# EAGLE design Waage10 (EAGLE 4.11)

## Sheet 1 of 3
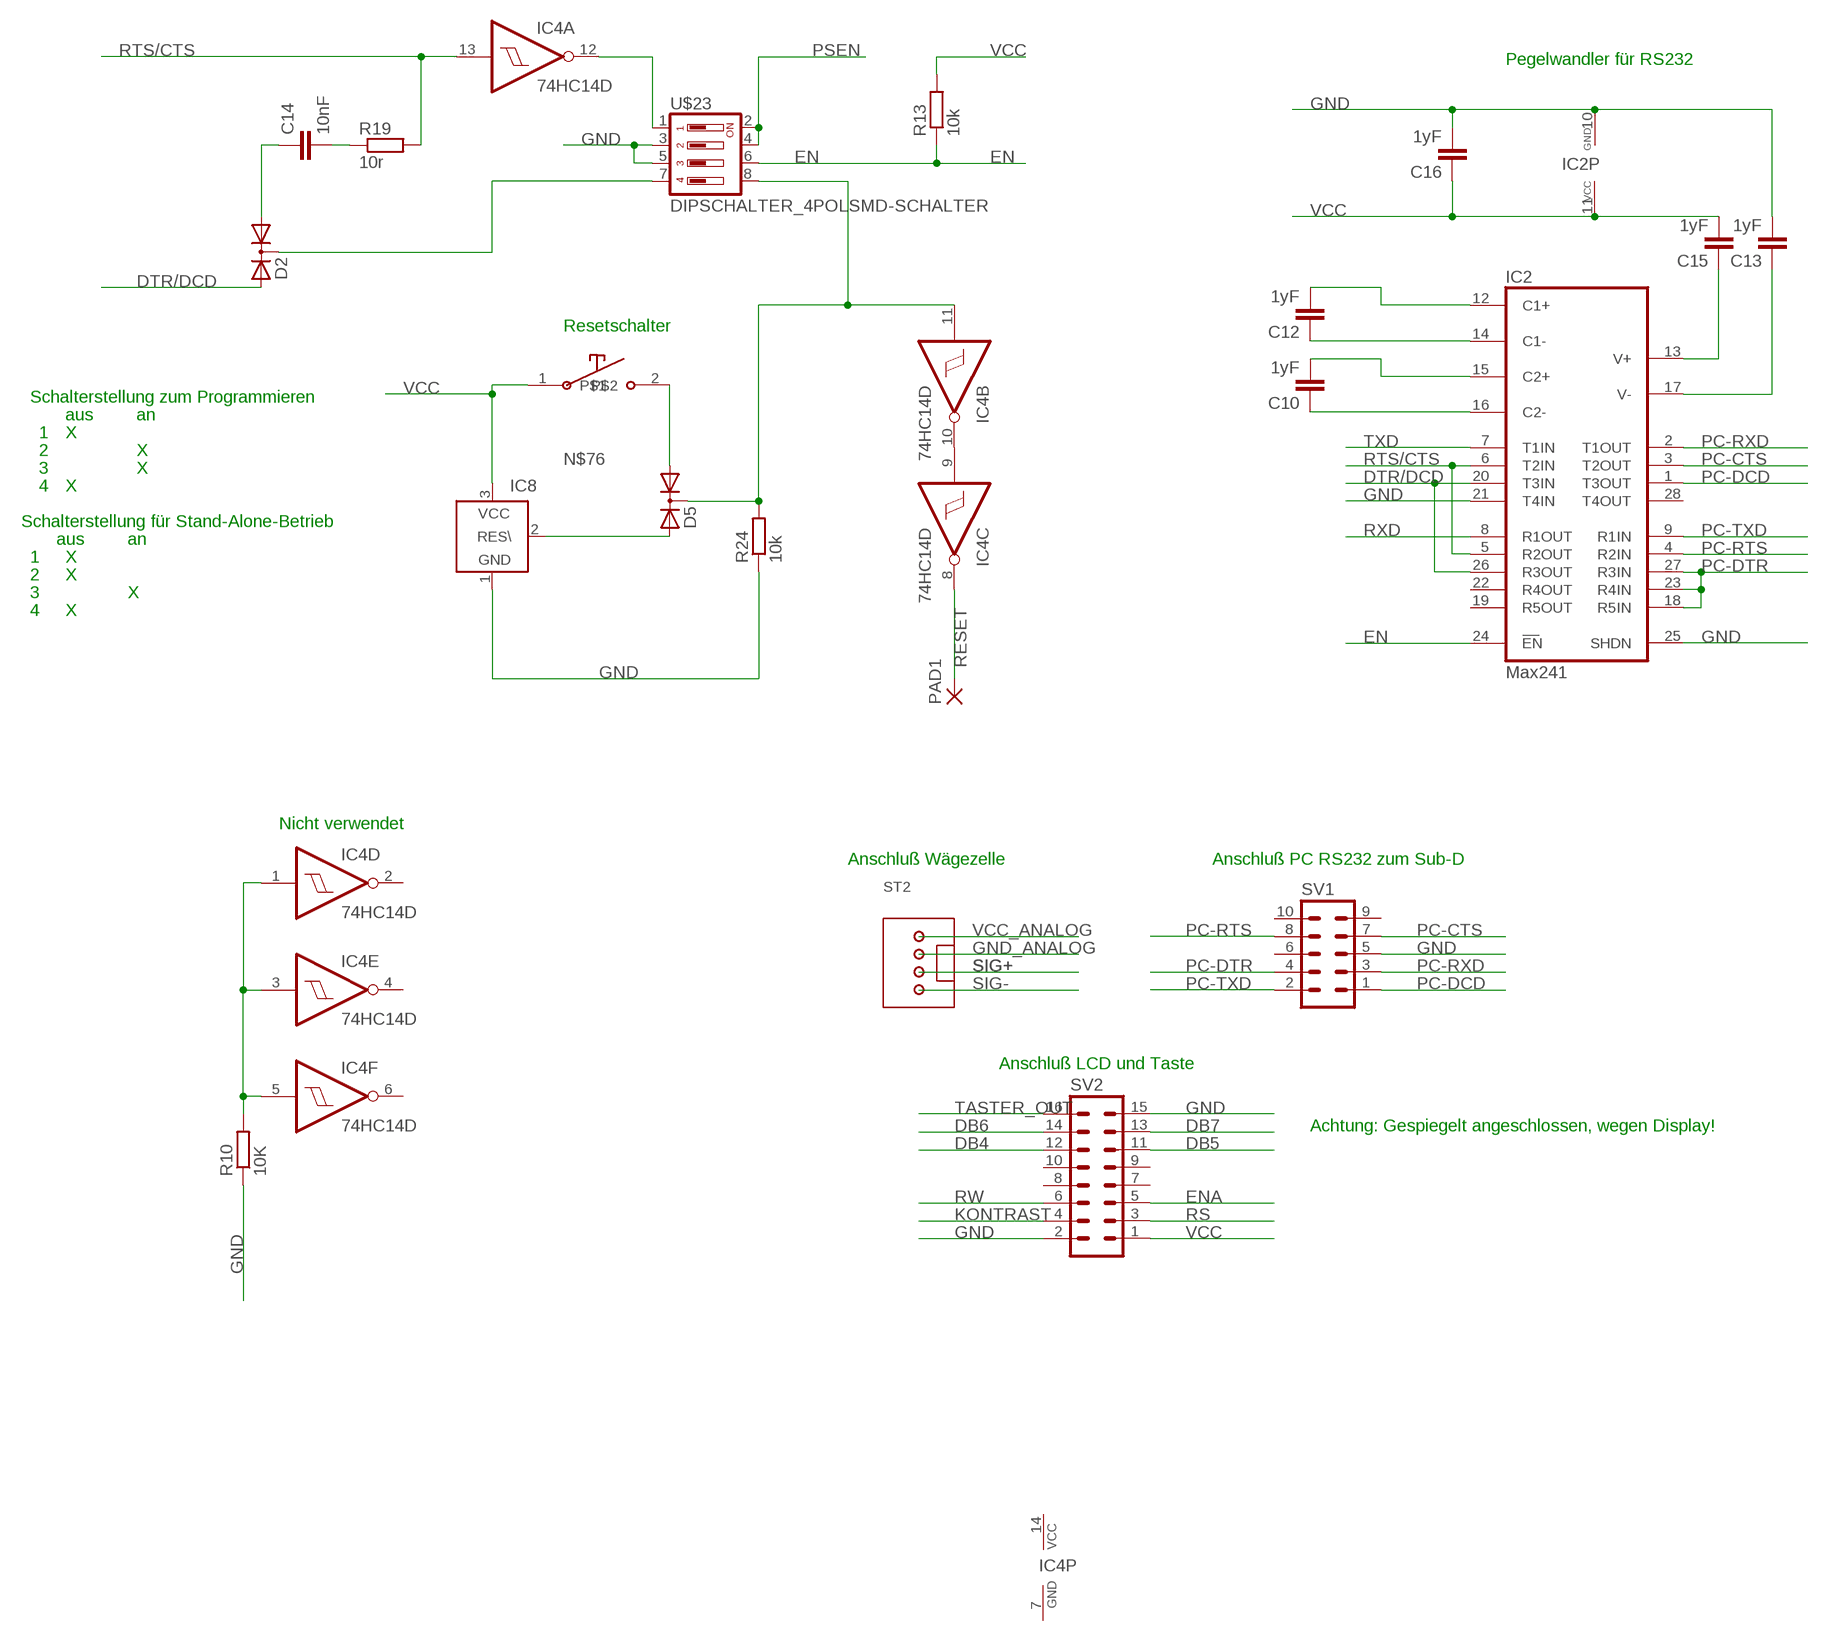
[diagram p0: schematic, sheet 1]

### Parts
C10  1yF  C-EUC1206  [C1206]
C12  1yF  C-EUC1206  [C1206]
C13  1yF  C-EUC1206  [C1206]
C14  10nF  C-EUC1206  [C1206]
C15  1yF  C-EUC1206  [C1206]
C16  1yF  C-EUC1206  [C1206]
D2  DIODE-2AC|CASOT23  [SOT23]
D5  DIODE-2AC|CASOT23  [SOT23]
IC2  Max241  MAX241ECWISSOP  [SSOP28]
IC4  74HC14D  [SO14]
IC8  TCM809  [SOT23B-3]
PAD1  SMD2  [SMD2]
R10  10K  R-EU_M1206  [M1206]
R13  10k  R-EU_M1206  [M1206]
R19  10r  R-EU_R1206  [R1206]
R24  10k  R-EU_R1206  [R1206]
ST2  MOLEX_04  [MOL_04SS]
SV1  ML10  [ML10]
SV2  ML16  [ML16]
U$4  TASTESMD-TASTE  [SMD-TASTE]
U$23  DIPSCHALTER_4POLSMD-SCHALTER  [SMD_DIP4]

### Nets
DB4: SV2.12 ; also sheet 2
DB5: SV2.11 ; also sheet 2
DB6: SV2.14 ; also sheet 2
DB7: SV2.13 ; also sheet 2
DTR/DCD: D2.2(A2) IC2.20(T3IN) IC2.26(R3OUT)
EN: IC2.24(EN) R13.1 U$23.6
ENA: SV2.5 ; also sheet 2
GND: C13.2 C16.2 IC2.10(GND) IC2.21(T4IN) IC2.25(SHDN) IC8.1(GND) R10.1 R24.1 SV1.5 SV2.2 SV2.15 U$23.3 U$23.5 ; also sheet 2,3
GND_ANALOG: ST2.2 ; also sheet 2,3
KONTRAST: SV2.4 ; also sheet 2
N$5: IC4.1(D:I) IC4.3(E:I) IC4.5(F:I) R10.2
N$7: IC4.9(C:I) IC4.10(B:O)
N$8: C14.1 D2.1(A1)
N$10: C14.2 R19.1
N$12: C10.2 IC2.15(C2+)
N$21: C12.1 IC2.14(C1-)
N$23: C12.2 IC2.12(C1+)
N$24: C10.1 IC2.16(C2-)
N$25: C13.1 IC2.17(V-)
N$26: C15.1 IC2.13(V+)
N$30: D2.3(C) U$23.7
N$76: D5.1(A1) U$4.2
N$78: D5.3(C) IC4.11(B:I) R24.2 U$23.8
N$84: IC4.12(A:O) U$23.1
N$87: D5.2(A2) IC8.2(RES\)
PC-CTS: IC2.3(T2OUT) SV1.7
PC-DCD: IC2.1(T3OUT) SV1.1
PC-DTR: IC2.18(R5IN) IC2.23(R4IN) IC2.27(R3IN) SV1.4
PC-RTS: IC2.4(R2IN) SV1.8
PC-RXD: IC2.2(T1OUT) SV1.3
PC-TXD: IC2.9(R1IN) SV1.2
PSEN: U$23.2 U$23.4 ; also sheet 2
RESET: IC4.8(C:O) PAD1.1(P) ; also sheet 2
RS: SV2.3 ; also sheet 2
RTS/CTS: IC2.5(R2OUT) IC2.6(T2IN) IC4.13(A:I) R19.2
RW: SV2.6 ; also sheet 2
RXD: IC2.8(R1OUT) ; also sheet 2
SIG+: ST2.3 ; also sheet 2
SIG-: ST2.4 ; also sheet 2
TASTER_OUT: SV2.16 ; also sheet 2
TXD: IC2.7(T1IN) ; also sheet 2
VCC: C15.2 C16.1 IC2.11(VCC) IC8.3(VCC) R13.2 SV2.1 U$4.1 ; also sheet 2,3
VCC_ANALOG: ST2.1 ; also sheet 2,3
Unconnected: IC2.19(R5OUT) IC2.22(R4OUT) IC2.28(T4OUT) SV1.6 SV1.9 SV1.10 SV2.7 SV2.8 SV2.9 SV2.10

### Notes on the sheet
- Pegelwandler für RS232
- Resetschalter
- Schalterstellung zum Programmieren
- aus | an
- 1 | X
- 2 | X
- 3 | X
- 4 | X
- Schalterstellung für Stand-Alone-Betrieb
- aus | an
- 1 | X
- 2 | X
- 3 | X
- 4 | X
- Nicht verwendet
- Anschluß Wägezelle | Anschluß PC RS232 zum Sub-D
- Anschluß LCD und Taste
- Achtung: Gespiegelt angeschlossen, wegen Display!

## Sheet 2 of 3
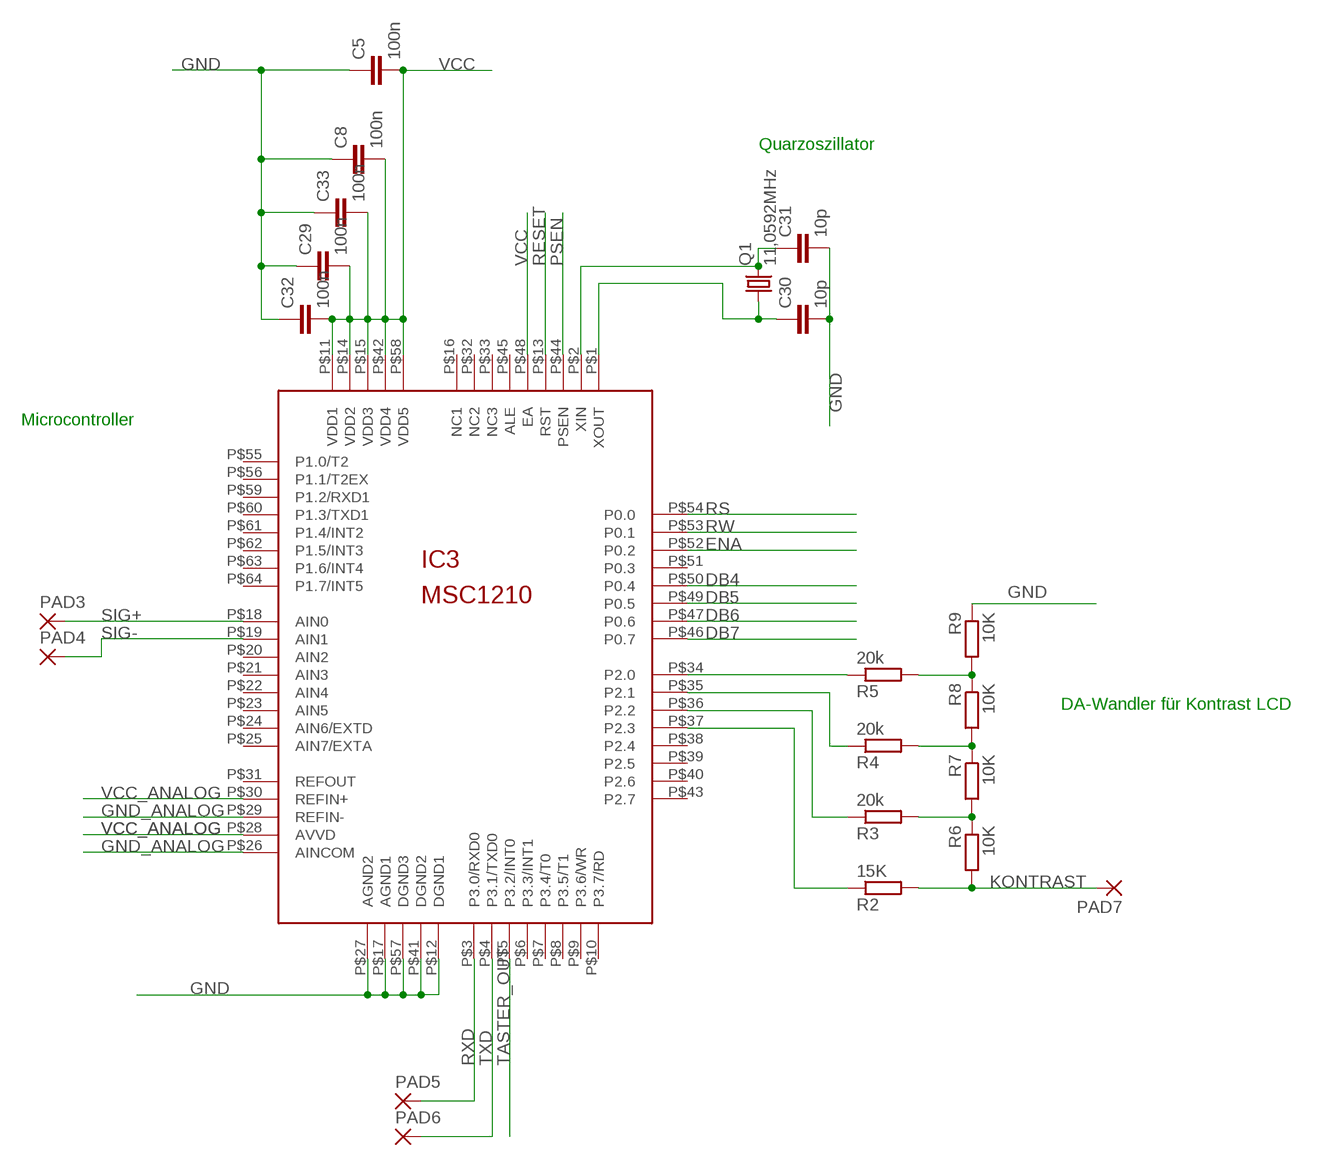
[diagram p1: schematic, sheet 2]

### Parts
C5  100n  C-EUC1206  [C1206]
C8  100n  C-EUC1206  [C1206]
C29  100n  C-EUC1206  [C1206]
C30  10p  C-EUC0805  [C0805]
C31  10p  C-EUC0805  [C0805]
C32  100n  C-EUC1206  [C1206]
C33  100n  C-EUC1206  [C1206]
IC3  MSC1210  MSC1210SMD  [S-PQFP-G64]
PAD3  SMD2  [SMD2]
PAD4  SMD2  [SMD2]
PAD5  SMD2  [SMD2]
PAD6  SMD2  [SMD2]
PAD7  SMD2  [SMD2]
Q1  11,0592MHz  CRYTALHC49UP  [HC49UP]
R2  15K  R-EU_M1206  [M1206]
R3  20k  R-EU_M1206  [M1206]
R4  20k  R-EU_M1206  [M1206]
R5  20k  R-EU_M1206  [M1206]
R6  10K  R-EU_M1206  [M1206]
R7  10K  R-EU_M1206  [M1206]
R8  10K  R-EU_M1206  [M1206]
R9  10K  R-EU_M1206  [M1206]

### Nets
DB4: IC3.P$50(P0.4) ; also sheet 1
DB5: IC3.P$49(P0.5) ; also sheet 1
DB6: IC3.P$47(P0.6) ; also sheet 1
DB7: IC3.P$46(P0.7) ; also sheet 1
ENA: IC3.P$52(P0.2) ; also sheet 1
GND: C5.1 C8.1 C29.1 C30.2 C31.2 C32.1 C33.1 IC3.P$12(DGND1) IC3.P$17(AGND1) IC3.P$27(AGND2) IC3.P$41(DGND2) IC3.P$57(DGND3) R9.1 ; also sheet 1,3
GND_ANALOG: IC3.P$26(AINCOM) IC3.P$29(REFIN-) ; also sheet 1,3
KONTRAST: PAD7.1(P) R2.2 R6.2 ; also sheet 1
N$1: IC3.P$34(P2.0) R5.1
N$3: C31.1 IC3.P$2(XIN) Q1.2
N$4: C30.1 IC3.P$1(XOUT) Q1.1
N$15: IC3.P$36(P2.2) R3.1
N$16: IC3.P$35(P2.1) R4.1
N$18: R3.2 R6.1 R7.2
N$19: R4.2 R7.1 R8.2
N$20: R5.2 R8.1 R9.2
N$28: IC3.P$37(P2.3) R2.1
PSEN: IC3.P$44(PSEN) ; also sheet 1
RESET: IC3.P$13(RST) ; also sheet 1
RS: IC3.P$54(P0.0) ; also sheet 1
RW: IC3.P$53(P0.1) ; also sheet 1
RXD: IC3.P$3(P3.0/RXD0) PAD5.1(P) ; also sheet 1
SIG+: IC3.P$18(AIN0) PAD3.1(P) ; also sheet 1
SIG-: IC3.P$19(AIN1) PAD4.1(P) ; also sheet 1
TASTER_OUT: IC3.P$5(P3.2/INT0) ; also sheet 1
TXD: IC3.P$4(P3.1/TXD0) PAD6.1(P) ; also sheet 1
VCC: C5.2 C8.2 C29.2 C32.2 C33.2 IC3.P$11(VDD1) IC3.P$14(VDD2) IC3.P$15(VDD3) IC3.P$42(VDD4) IC3.P$48(EA) IC3.P$58(VDD5) ; also sheet 1,3
VCC_ANALOG: IC3.P$28(AVVD) IC3.P$30(REFIN+) ; also sheet 1,3
Unconnected: IC3.P$6(P3.3/INT1) IC3.P$7(P3.4/T0) IC3.P$8(P3.5/T1) IC3.P$9(P3.6/WR) IC3.P$10(P3.7/RD) IC3.P$16(NC1) IC3.P$20(AIN2) IC3.P$21(AIN3) IC3.P$22(AIN4) IC3.P$23(AIN5) IC3.P$24(AIN6/EXTD) IC3.P$25(AIN7/EXTA) IC3.P$31(REFOUT) IC3.P$32(NC2) IC3.P$33(NC3) IC3.P$38(P2.4) IC3.P$39(P2.5) IC3.P$40(P2.6) IC3.P$43(P2.7) IC3.P$45(ALE) IC3.P$51(P0.3) IC3.P$55(P1.0/T2) IC3.P$56(P1.1/T2EX) IC3.P$59(P1.2/RXD1) IC3.P$60(P1.3/TXD1) IC3.P$61(P1.4/INT2) IC3.P$62(P1.5/INT3) IC3.P$63(P1.6/INT4) IC3.P$64(P1.7/INT5)

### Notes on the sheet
- Quarzoszillator
- Microcontroller
- DA-Wandler für Kontrast LCD

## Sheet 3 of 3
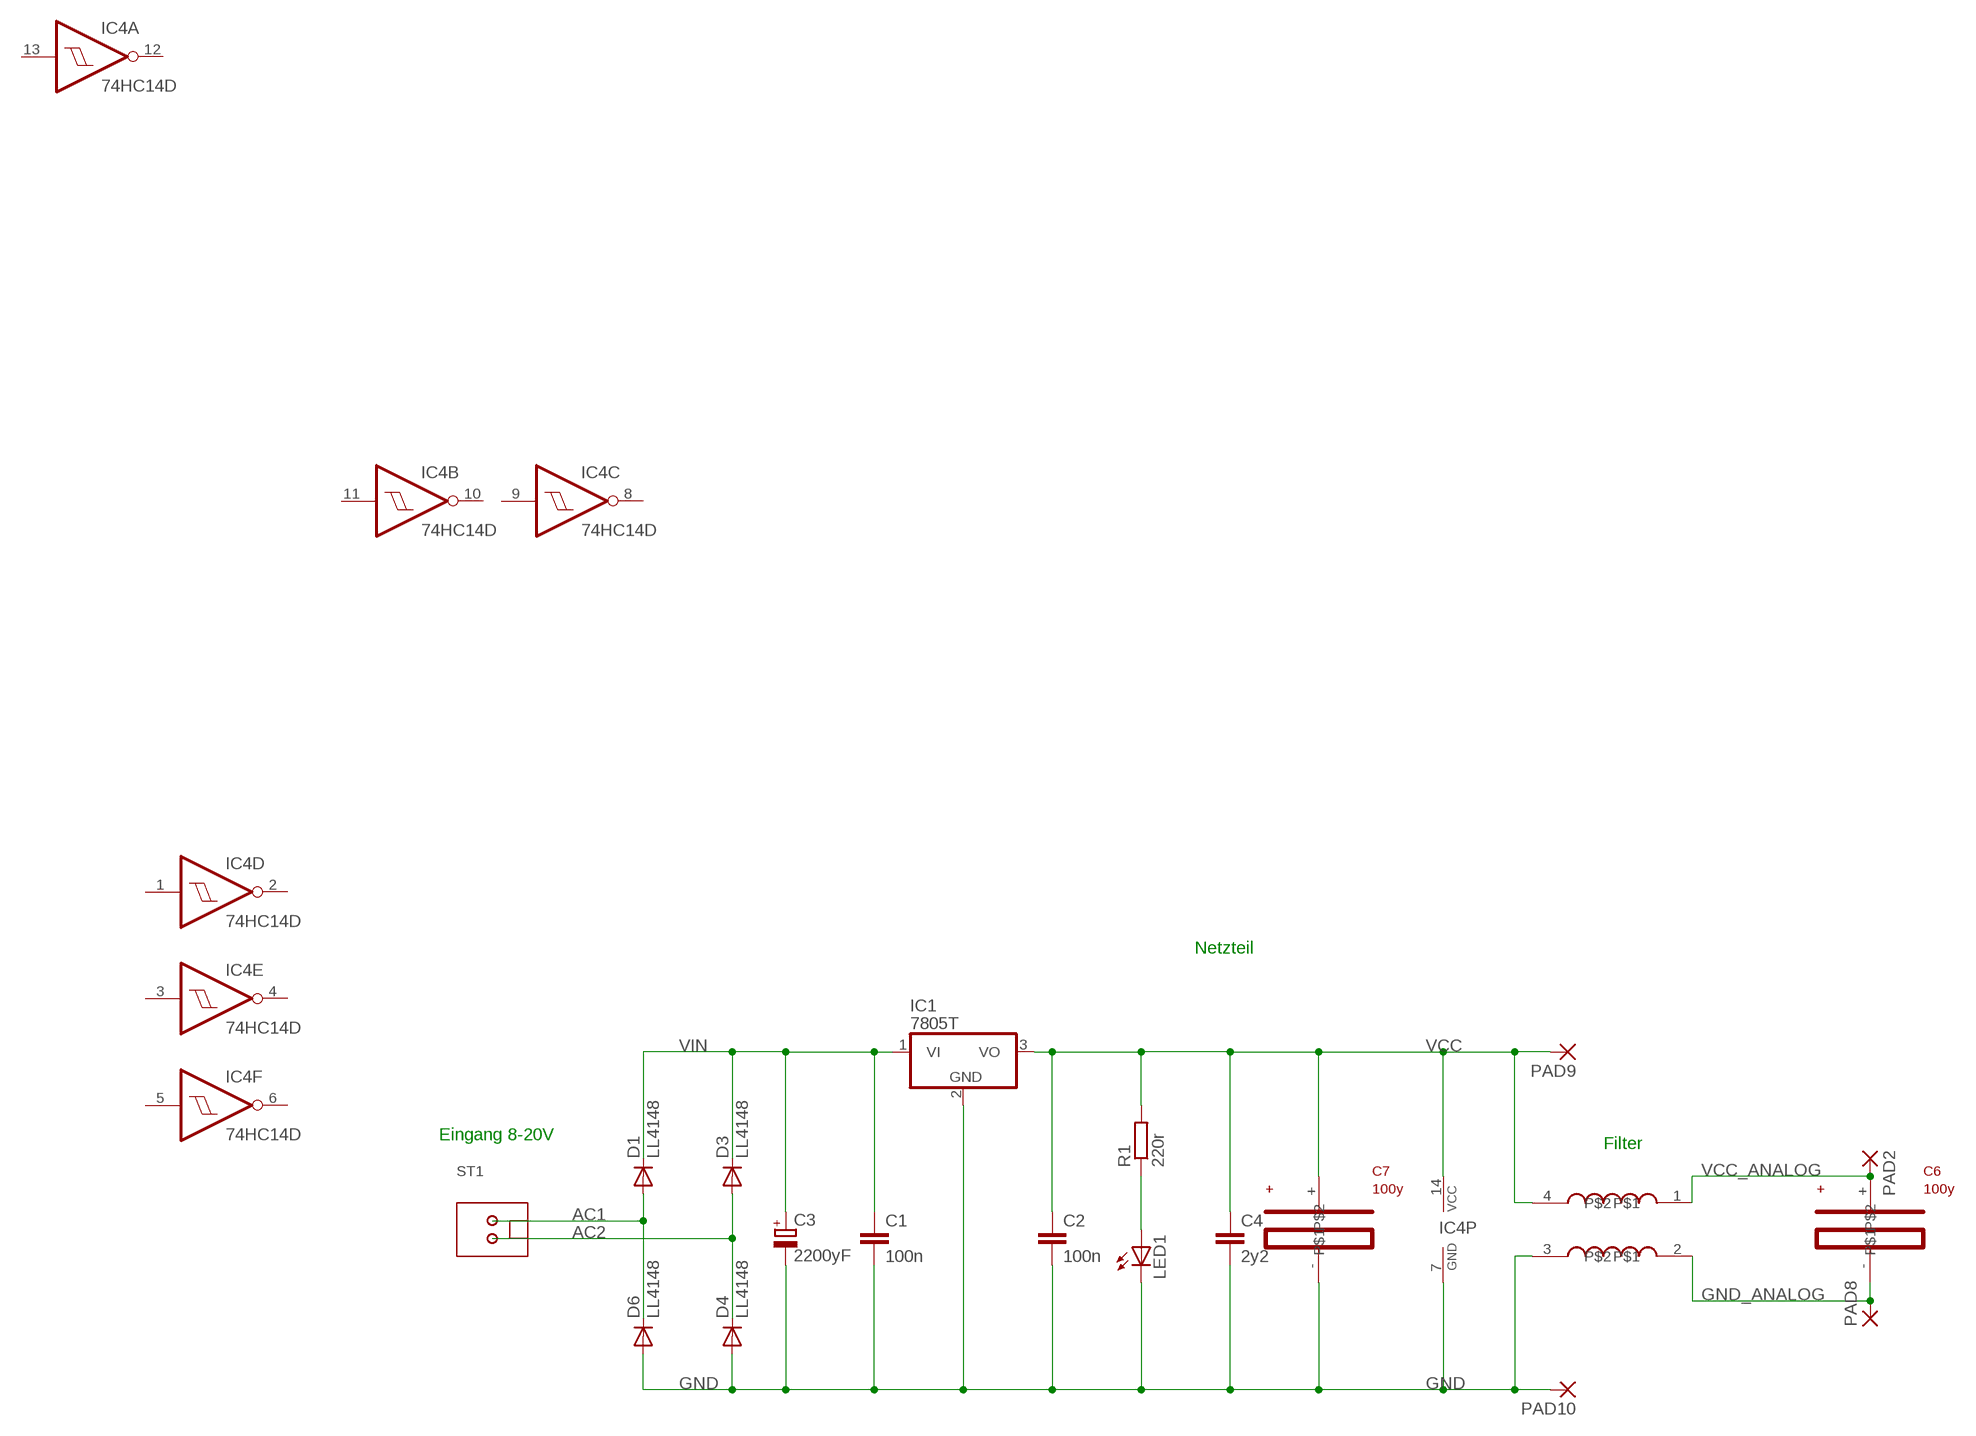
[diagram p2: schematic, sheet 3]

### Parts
C1  100n  C-EUC1206  [C1206]
C2  100n  C-EUC1206  [C1206]
C3  2200yF  CPOL-EUE7.5-16  [E7,5-16]
C4  2y2  C-EUC1206  [C1206]
C6  100y  ELKO_SMD  [SMD_D]
C7  100y  ELKO_SMD  [SMD_D]
D1  LL4148  DIODE-SOD80C  [SOD80C]
D3  LL4148  DIODE-SOD80C  [SOD80C]
D4  LL4148  DIODE-SOD80C  [SOD80C]
D6  LL4148  DIODE-SOD80C  [SOD80C]
F1  FILTER  [FILTER]
IC1  7805T  [TO220H]
LED1  LEDSMT1206  [1206]
PAD2  SMD2  [SMD2]
PAD8  SMD2  [SMD2]
PAD9  SMD2  [SMD2]
PAD10  SMD2  [SMD2]
R1  220r  R-EU_M1206  [M1206]
ST1  MOLEX_02  [MOL_02SS]

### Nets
AC1: D1.A D6.C ST1.1
AC2: D3.A D4.C ST1.2
GND: C1.2 C2.2 C3.- C4.2 C7.- D4.A D6.A F1.3 IC1.2(GND) IC4.7(P:GND) LED1.C PAD10.1(P) ; also sheet 1,2
GND_ANALOG: C6.- F1.2 PAD8.1(P) ; also sheet 1,2
N$13: LED1.A R1.1
VCC: C2.1 C4.1 C7.+ F1.4 IC1.3(VO) IC4.14(P:VCC) PAD9.1(P) R1.2 ; also sheet 1,2
VCC_ANALOG: C6.+ F1.1 PAD2.1(P) ; also sheet 1,2
VIN: C1.1 C3.+ D1.C D3.C IC1.1(VI)
Unconnected: IC4.2(D:O) IC4.4(E:O) IC4.6(F:O)

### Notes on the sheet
- Netzteil
- Eingang 8-20V
- Filter

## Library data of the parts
C1 C2 C4 C5 C8 C10 C12-C16 C29-C33 = rcl:C-EU: CAPACITOR, European symbol
C3 = rcl:CPOL-EU: POLARIZED CAPACITOR, European symbol
C6 C7 = FRANK:ELKO_SMD
D1 D3 D4 D6 = DIODE:DIODE-: DIODE
D2 D5 = DIODE:DIODE-2AC|CA: Dual DIODE Anode-Cathode|Cathode-Anode
F1 = FRANK:FILTER
IC1 = linear:78*: Positive VOLTAGE REGULATOR
IC2 = maxim:MAX241ECWI: RS232 TRANSEIVER Achtung: ECWI = SO28L ECAI=SSOP28
IC3 = FRANK:MSC1210
IC4 = 74xx-eu:74*14: Hex schmitt trigger INVERTER
IC8 = telcom:TCM809: POWER SUPPLY MONITOR replacement for Maxim MAX809 and MAX810
LED1 = led:LED: LED
PAD1-PAD10 = wirepad:SMD2: SMD PAD
Q1 = crystal:CRYTAL: CRYSTAL
R1-R10 R13 R19 R24 = rcl:R-EU_: RESISTOR, European symbol
ST1 = CONNECT:MOLEX_02
ST2 = CONNECT:MOLEX_04
SV1 = con-ml:ML10: HARTING
SV2 = con-ml:ML16: HARTING
U$4 = FRANK:TASTE
U$23 = FRANK:DIPSCHALTER_4POL

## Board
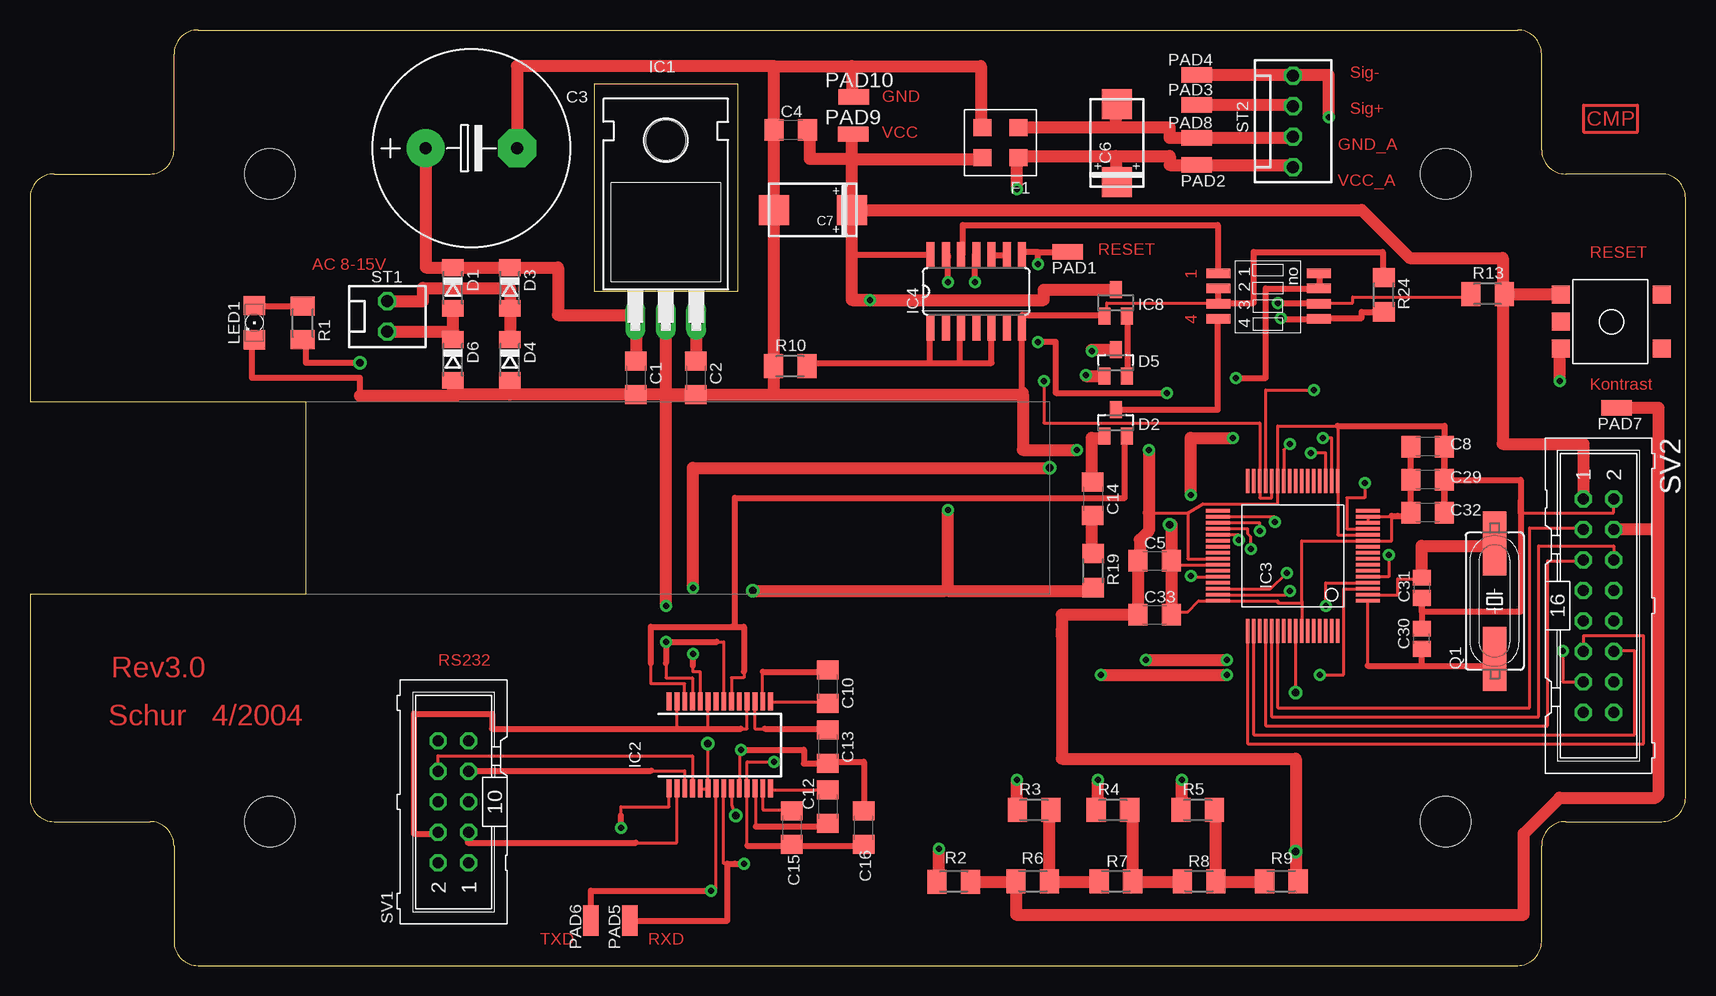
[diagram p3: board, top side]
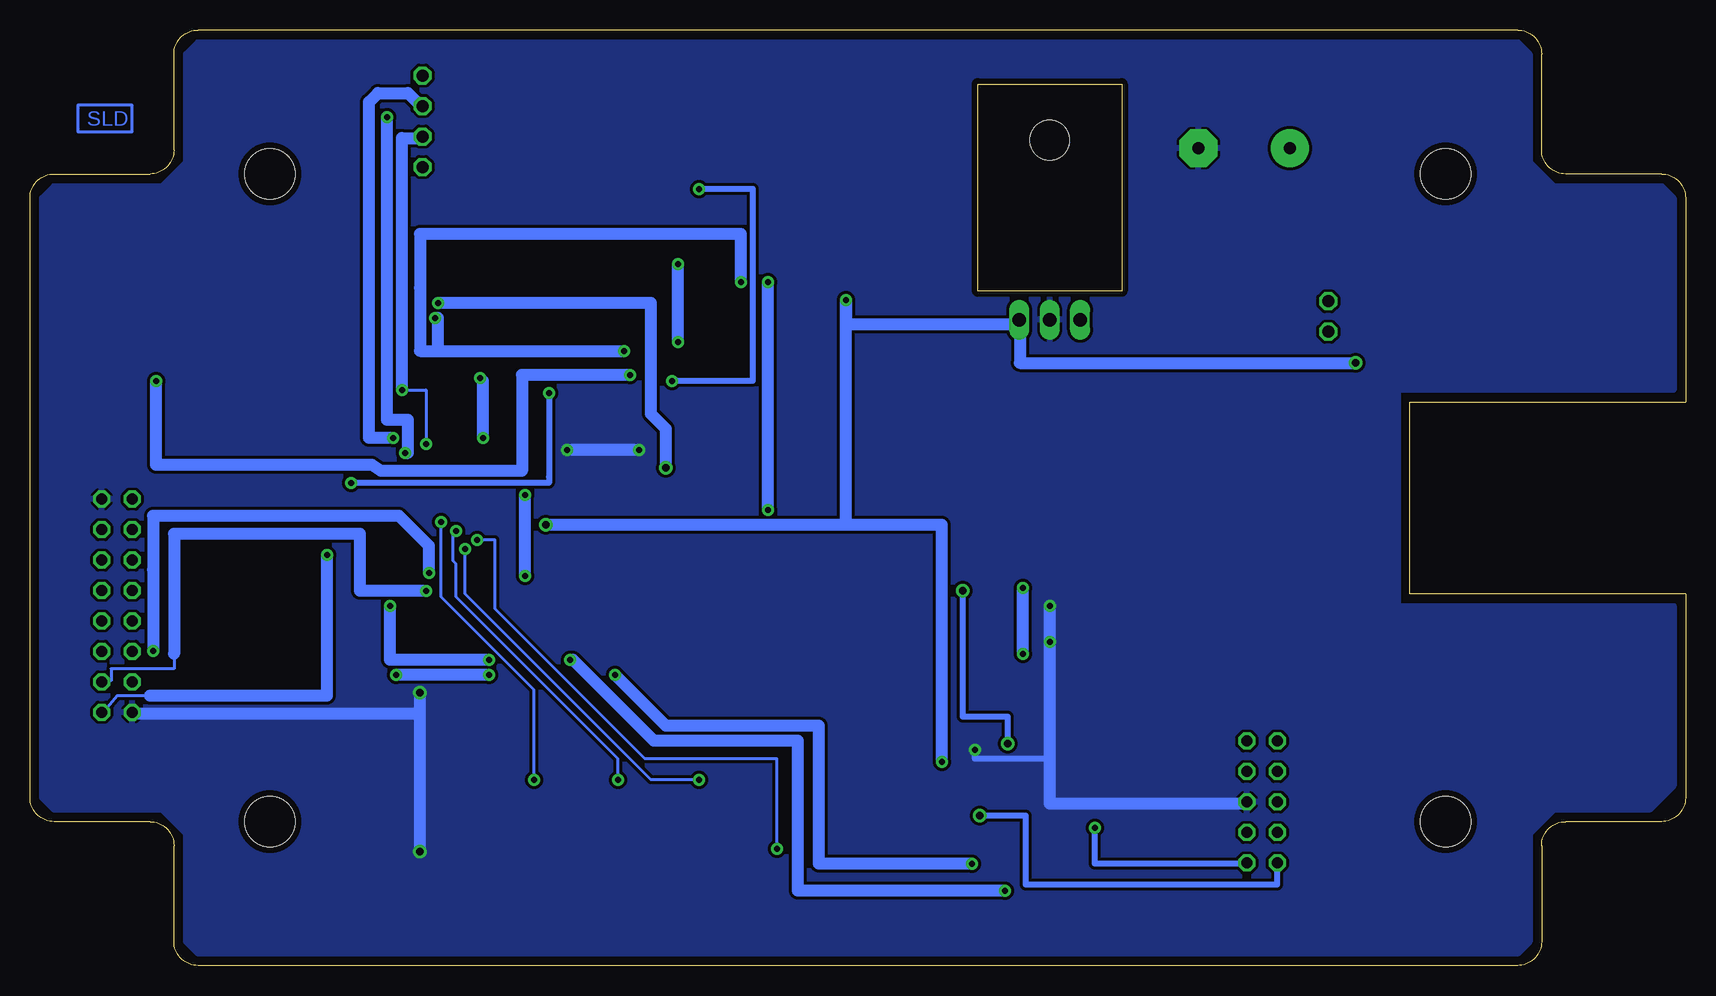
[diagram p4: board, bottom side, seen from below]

Size 138 x 78 mm. Coordinates in mm from the lower left corner, seen from the top.
Outline: 14,0 124,0 arc90 126,2 126,10 arc-90 128,12 136,12 arc90 138,14 138,64 arc90 136,66 128,66 arc-90 126,68 126,76 arc90 124,78 14,78 arc90 12,76 12,68 arc-90 10,66 2,66 arc90 0,64 0,47 23,47 23,31 0,31 0,14 arc90 2,12 10,12 arc-90 12,10 12,2 arc90 14,0
Outline: 47,56.25 59,56.25 59,73.5 47,73.5 47,56.25
Copper layers (1*16): Top 0.035mm / dielectric 1.5mm / Bottom 0.035mm
Design rules "default": minimum track width 0.25mm, minimum drill 0.4mm, track to track 0.25mm, track to pad 0.2mm, pad to pad 0.2mm, via to via 0.25mm, smd to smd 0.25mm, copper to edge 0.5mm, drill to drill 0.5mm, minimum pad ring 0.25mm, minimum via ring 0.25mm, stop-mask expansion 0.2mm, vias tented up to drill 0mil, thermal gap 0.2mm
Holes 4.2 mm at 20,12 20,66 118,66 118,12

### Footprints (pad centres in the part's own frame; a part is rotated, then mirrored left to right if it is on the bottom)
C1206 = smd 1.6 x 1.8: 1 -1.4,0; 2 1.4,0
E7,5-16 = drill 1.016 pad 3.15 round: + -3.81,0 | drill 1.016 pad 3.15 octagon: - 3.81,0
SMD_D = smd 2.5 x 2.5: + 0,0; - 6.5,0
C0805 = smd 1.3 x 1.5: 1 -0.85,0; 2 0.85,0
SOD80C = smd 1.4 x 1.8: A 1.7,0; C -1.7,0
SOT23 = smd 1 x 1.4: 1 -0.95,-1.1; 2 0.95,-1.1; 3 0,1.1
FILTER = smd 1.5 x 1.4: 1 0,2.5; 2 0,0; 3 3,0; 4 3,2.5
TO220H = drill 1.118 long: 1 -2.54,-10.16; 2 0,-10.16; 3 2.54,-10.16 | hole 3.302: 0,4.826
SSOP28 = smd 0.4 x 1.5: 1 -4.225,-3.625; 2 -3.575,-3.625; 3 -2.925,-3.625; 4 -2.275,-3.625; 5 -1.625,-3.625; 6 -0.975,-3.625; 7 -0.325,-3.625; 8 0.325,-3.625; 9 0.975,-3.625; 10 1.625,-3.625; 11 2.275,-3.625; 12 2.925,-3.625; 13 3.575,-3.625; 14 4.225,-3.625; 15 4.225,3.625; 16 3.575,3.625; 17 2.925,3.625; 18 2.275,3.625; 19 1.625,3.625; 20 0.975,3.625; 21 0.325,3.625; 22 -0.325,3.625; 23 -0.975,3.625; 24 -1.625,3.625; 25 -2.275,3.625; 26 -2.925,3.625; 27 -3.575,3.625; 28 -4.225,3.625
S-PQFP-G64 = smd 0.3 x 2: P$1 0,-0.5; P$2 0.5,-0.5; P$3 1,-0.5; P$4 1.5,-0.5; P$5 2,-0.5; P$6 2.5,-0.5; P$7 3,-0.5; P$8 3.5,-0.5; P$9 4,-0.5; P$10 4.5,-0.5; P$11 5,-0.5; P$12 5.5,-0.5; P$13 6,-0.5; P$14 6.5,-0.5; P$15 7,-0.5; P$16 7.5,-0.5; P$33 7.5,12; P$34 7,12; P$35 6.5,12; P$36 6,12; P$37 5.5,12; P$38 5,12; P$39 4.5,12; P$40 4,12; P$41 3.5,12; P$42 3,12; P$43 2.5,12; P$44 2,12; P$45 1.5,12; P$46 1,12; P$47 0.5,12; P$48 0,12 | smd 2 x 0.3: P$17 10,2; P$18 10,2.5; P$19 10,3; P$20 10,3.5; P$21 10,4; P$22 10,4.5; P$23 10,5; P$24 10,5.5; P$25 10,6; P$26 10,6.5; P$27 10,7; P$28 10,7.5; P$29 10,8; P$30 10,8.5; P$31 10,9; P$32 10,9.5; P$49 -2.5,9.5; P$50 -2.5,9; P$51 -2.5,8.5; P$52 -2.5,8; P$53 -2.5,7.5; P$54 -2.5,7; P$55 -2.5,6.5; P$56 -2.5,6; P$57 -2.5,5.5; P$58 -2.5,5; P$59 -2.5,4.5; P$60 -2.5,4; P$61 -2.5,3.5; P$62 -2.5,3; P$63 -2.5,2.5; P$64 -2.5,2
SO14 = smd 0.66 x 2.032: 1 -3.81,-3.073; 2 -2.54,-3.073; 3 -1.27,-3.073; 4 0,-3.073; 5 1.27,-3.073; 6 2.54,-3.073; 7 3.81,-3.073; 8 3.81,3.073; 9 2.54,3.073; 10 1.27,3.073; 11 0,3.073; 12 -1.27,3.073; 13 -2.54,3.073; 14 -3.81,3.073
SOT23B-3 = smd 1 x 1.4: 1 -0.95,-1.1; 2 0.95,-1.1; 3 0,1.1
1206 = smd 1.6 x 1.803: A -1.422,0; C 1.422,0
SMD2 = smd 1.27 x 2.54: 1 0,0
HC49UP = smd 5.334 x 1.93: 1 -4.826,0; 2 4.826,0
M1206 = smd 1.6 x 2: 1 -1.4,0; 2 1.4,0
R1206 = smd 1.6 x 1.803: 1 -1.422,0; 2 1.422,0
MOL_02SS = drill 1 pad 1.4 octagon: 1 0,0; 2 2.54,0
MOL_04SS = drill 1 pad 1.4 octagon: 1 0,0; 2 2.54,0; 3 5.08,0; 4 7.62,0
ML10 = drill 0.914 octagon: 1 -5.08,-1.27; 2 -5.08,1.27; 3 -2.54,-1.27; 4 -2.54,1.27; 5 0,-1.27; 6 0,1.27; 7 2.54,-1.27; 8 2.54,1.27; 9 5.08,-1.27; 10 5.08,1.27
ML16 = drill 0.914 octagon: 1 -8.89,-1.27; 2 -8.89,1.27; 3 -6.35,-1.27; 4 -6.35,1.27; 5 -3.81,-1.27; 6 -3.81,1.27; 7 -1.27,-1.27; 8 -1.27,1.27; 9 1.27,-1.27; 10 1.27,1.27; 11 3.81,-1.27; 12 3.81,1.27; 13 6.35,-1.27; 14 6.35,1.27; 15 8.89,-1.27; 16 8.89,1.27
SMD-TASTE = smd 1.5 x 1.5: 1 0,2.25; 2 0,-2.25; 3 8.4,2.25; 4 8.4,-2.25; 5 0,0
SMD_DIP4 = smd 0.8 x 2: 1 0,-8.4; 2 0,0; 3 1.27,-8.4; 4 1.27,0; 5 2.54,-8.4; 6 2.54,0; 7 3.81,-8.4; 8 3.81,0

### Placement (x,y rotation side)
C1  50.5,49 270 top
C2  55.5,49 270 top
C3  36.79,68.14 0 top
C4  63.42,69.66 180 top
C5  93.75,33.75 0 top
C6  90.61,65.33 90 top
C7  68.5,63 180 top
C8  116.5,43.25 180 top
C10  66.5,23.25 270 top
C12  66.5,13.25 270 top
C13  66.5,18.25 270 top
C14  88.59,38.92 270 top
C15  63.5,11.5 270 top
C16  69.5,11.5 90 top
C29  116.5,40.5 180 top
C30  116,27.25 90 top
C31  116,31.5 270 top
C32  116.5,37.75 180 top
C33  93.75,29.25 0 top
D1  35.25,56.5 270 top
D2  90.5,45.25 0 top
D3  40,56.5 270 top
D4  40,50.5 270 top
D5  90.5,50.25 0 top
D6  35.25,50.5 270 top
F1  82.38,69.86 180 top
IC1  53,64 0 top
IC2  57.5,18.39 0 top
IC3  111,30.41 90 top
IC4  78.88,56.21 0 top
IC8  90.5,55.25 0 top
LED1  18.7,53.59 270 top
PAD1  86.5,59.5 90 top
PAD2  97.25,66.75 90 top
PAD3  97.25,71.75 270 top
PAD4  97.25,74.25 270 top
PAD5  50,3.75 0 top
PAD6  46.75,3.75 0 top
PAD7  132.25,46.5 90 top
PAD8  97.25,69 270 top
PAD9  68.64,69.31 270 top
PAD10  68.65,72.41 270 top
Q1  122.09,30.38 90 top
R1  22.74,53.58 270 top
R2  77,7 0 top
R3  83.7,12.96 0 top
R4  90.27,12.96 0 top
R5  97.34,12.96 0 top
R6  83.59,7.04 180 top
R7  90.52,7.04 180 top
R8  97.45,7.04 180 top
R9  104.31,7.04 180 top
R10  63.37,49.96 0 top
R13  121.5,56 0 top
R19  88.62,32.92 270 top
R24  112.85,55.92 270 top
ST1  29.79,52.84 90 top
ST2  105.29,66.58 90 top
SV1  35.31,13.64 90 top
SV2  130.75,30 270 top
U$4  127.6,53.68 0 top
U$23  107.45,57.72 270 top

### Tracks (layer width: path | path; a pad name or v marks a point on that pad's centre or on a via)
AC1
  Top 1: D6.C 35.5,52.2 35.5,52.34 35.25,52.84 | ST1.1 35.25,52.84 | 35.25,52.84 35.25,52.25 | 35.25,52.84 D1.A
AC2
  Top 1: ST1.2 32.75,55.38 32.75,56.5 40,56.5 D3.A D4.C
DB4
  Top 0.25: 132.02,26.25 132,26.25 | 132.02,26.25 SV2.12 | 132.02,26.25 133.75,26.25 133.75,19.25 102,19.25 IC3.P$50
DB5
  Top 0.25: SV2.11 129.48,27.5 134.5,27.5 134.5,18.5 101.5,18.5 IC3.P$49
DB6  (via drill 0.5)
  Top 0.25: IC3.P$47 104.66,30.91 v105,31.25
  Bottom 0.25: 126,26 126,24.75 131.25,24.75 131.25,23.75 132.02,23.75 SV2.14
  Bottom 1: v105,31.25 110.5,31.25 110.5,36 126,36 126,26
DB7  (via drill 0.5)
  Top 0.25: SV2.13 127.75,23.65 v127.75,26.25 | IC3.P$46 103.41,31.41 v104.75,32.75
  Bottom 0.25: 127.75,33 128,33
  Bottom 1: v127.75,26.25 127.75,33 127.75,37.5 107.25,37.5 104.75,35 v104.75,32.75
DTR/DCD
  Top 0.25: IC2.20 58.48,24 59.5,24 59.5,24.51 | IC2.26 54.58,23.5 51.75,23.5 51.75,25.2
  Top 0.5: 59.5,24.51 59.5,28.25 58.5,28.25 | 58.5,28.25 51.75,28.25 51.75,25.2 | D2.2 91.25,44.15 91.25,39 58.75,39 58.75,28.25 58.5,28.25
EN  (via drill 0.5, 0.61)
  Top 0.25: 120.1,55.75 110.25,55.75 110.25,55.25 107.5,55.25 | IC2.24 55.88,24.5 55.25,24.5 55.25,25
  Top 0.5: 120.1,55.75 R13.1 | 107.5,55.25 107.45,55.25 U$23.6 107.5,55.18 107.5,55.25 | 55.25,25 v55.25,26 | v104,55.25 107.5,55.25
  Top 1: v85,41.5 55.25,41.5 v55.25,31.5
  Bottom 1: v55.25,26 v55.25,31.5 | v104,55.25 86.25,55.25 86.25,46 85,44.75 v85,41.5
ENA
  Top 0.25: IC3.P$52 103,20 126.5,20 126.5,33.75 129.5,33.75 129.5,33.81 SV2.5
GND  (via drill 0.5, 0.61 pad 0.5)
  Top 0.25: 89.55,54.25 89.75,54.25 89.75,55.25 99,55.25 | 116,30.75 C31.2 | 93.25,37.75 96.5,37.75 | 82.75,47.5 82.75,47 | R9.1 105.71,7 105.5,7 | SV2.2 132.02,37.75 124.25,37.75 | IC3.P$41 96.5,33.91 96.5,37.75 | 109,40.5 109,45 104,45 IC3.P$27 104,38.5 97.75,38.5 96.5,37.75 | 109,40.5 IC3.P$17 | IC3.P$12 109,35.91 109,40.5 | v105.5,22.75 IC3.P$57 | 53,25.22 53,24 55.23,24 IC2.25 | IC2.21 57.83,27 57.25,27 | 59.12,18 IC2.10 | v59.25,18 59.12,18 | 59.12,18 59,18 | C13.2 66.5,17
  Top 0.5: 99.05,56.5 U$23.3 | 99.05,56.5 U$23.5 99,55.18 99,55.25 102,55.25 102,59.5 112.75,59.5 112.75,57.34 R24.1 | 99.05,56.5 99,56.5 | 82.75,47.5 82.69,47.5 IC4.7 82.69,54.25 89.55,54.25 IC8.1 | 57.25,27 v53,27 53,25.22 | C31.2 C30.2 | 116,30.75 116,29.5 124.25,29.5 124.25,37.75 | 124.25,37.75 124.25,38.75 | LED1.C 18.5,52.17 18.5,49 27.5,49 27.5,47.5 | 35.5,47.6 35.5,47.5 | 118,40.5 C29.1 117.9,37.6 | C8.1 117.9,40.6 118,40.5 | 117.9,37.6 C32.1 | 117.9,37.6 118,37.5 | 124.25,37.75 124.25,40.5 118,40.5 | 117.9,37.6 117.9,45 109,45 | C13.2 64.5,16.85 64.5,18 59.12,18 | C16.2 69.5,17 66.5,17
  Top 1: F1.3 79.25,69.86 79.25,75 68.5,75 | v53,30 53,47.5 | 53,47.5 IC1.2 | 82.75,47.5 82.75,43 v87.25,43 | 82.75,47.5 82.75,47.75 | v93.25,43 93.25,37.75 93.25,36.25 92.5,35.5 92.5,33.5 92.35,33.65 C5.1 C33.1 | R9.1 105.75,7.08 | 105.5,7 v105.5,9.5 105.5,17.25 86,17.25 86,27.5 | C2.2 C1.2 | C2.2 C1.2 | C2.2 55.5,47.5 53,47.5 | 40,48.75 D4.A 40,47.6 | C3.- 40.6,75 62,75 | 62,75 68.5,75 | 86,27.5 86,28 | C2.2 62,47.6 | 62,47.6 82.75,47.6 82.75,47.5 | 40,47.6 35.5,47.6 35.25,47.6 D6.A | C1.2 40,47.6 | 35.5,47.5 27.5,47.5 | C33.1 92.35,29.15 92.5,29 | C33.1 86,29.25 86,27.5 | C4.2 62,69.66 62,70 | 62,70 62,75 | 62,70 C7.- 62,49.96 | 62,49.96 R10.1 | 62,47.6 62,49.96 | PAD10.1 68.5,72.41 68.5,75
  Bottom 0.25: 129.48,21 SV2.15
  Bottom 0.5: 53,17.25 59.25,17.25 v59.25,18 | SV1.5 36.58,13.5
  Bottom 1: v53,30 v53,27 53,17.25 53,13.5 36.58,13.5 | v87.25,43 v93.25,43 | 105.5,21 v105.5,22.75 | v105.5,9.5 105.5,21 | 105.5,21 129.48,21
  pour Bottom: 1,30 1,15 3,13 11,13 13,11 13,2 14,1 124,1 125,2 125,11 127,13 136,13 137,14 137,64 136,65 127,65 125,67 125,76 124,77 14,77 13,76 13,67 11,65 2,65 1,64 1,48 24,48 24,30
GND_ANALOG  (via drill 0.5)
  Top 0.25: v107,48 103,48 IC3.P$29 | ST2.2 105.29,69 | IC3.P$26 104.5,43 v105,43.5
  Top 0.5: 105.29,69 105.25,69
  Top 1: C6.- 90.75,71.83 90.75,71.75 90.5,71.75 90.5,69.86 | 105.25,69 PAD8.1 95,69 95,69.86 90.5,69.86 | 90.5,69.86 F1.2
  Bottom 0.25: 105.29,69 ST2.2 | v105,43.5 105,48 v107,48
  Bottom 1: v107,48 107,69 105.29,69
KONTRAST
  Top 0.5: 82.19,7 R6.2 | 135.75,36.5 135.75,36.35
  Top 1: R2.2 82.19,7 | R6.2 82.19,4.25 124.5,4.25 124.5,11 127.5,14 135.5,14 135.75,14.25 135.75,36.5 135.75,46.5 PAD7.1 | 135.75,36.35 SV2.4
N$1  (via drill 0.5)
  Top 0.25: 96,13 95.98,13 R5.1 | IC3.P$34 103.75,37.41 v103.75,37
  Top 1: 96,13 v96,15.5
  Bottom 0.25: v103.75,37 103.75,30.75 96,23 v96,15.5
N$2
  Top 0.25: 129.5,71.75 134,71.75 134,69.5 129.5,69.5 129.5,71.75
N$3
  Top 0.25: C31.1 115.75,32.35 115.75,32.25 114,32.25 114,30.91 IC3.P$2
  Top 0.406: 122.09,35 Q1.2
  Top 1: C31.1 116,35 122.09,35
N$4
  Top 0.25: 111.5,25 IC3.P$1
  Top 0.406: Q1.1 122.09,25.5 122,25.5 122,25
  Top 0.5: 116,25 C30.1 | 116,25 122,25 | 111.5,25 116,25
N$5
  Top 0.5: IC4.1 75.07,53 75,53 75,50.25 | IC4.3 77.61,52.75 77.5,52.75 77.5,50.25 | IC4.5 80.15,50.25 77.5,50.25 | 75,50.25 77.5,50.25 | R10.2 65,49.96 65,50.25 75,50.25
N$6
  Bottom 0.25: 129.5,71.75 134,71.75 134,69.5 129.5,69.5 129.5,71.75
N$7
  Top 0.5: IC4.9 81.42,59.25 80.15,59.25 IC4.10
N$8
  Top 0.5: C14.1 88.5,40.32 | 89.5,44 89.5,44.15 D2.1
  Top 1: 88.5,40.32 88.5,44 89.5,44
N$10
  Top 0.5: C14.2 88.75,37.52
  Top 1: R19.1 88.5,34.34 88.5,37.52 C14.2
N$12
  Top 0.25: C10.2 66.5,22 61.73,22 IC2.15
N$13
  Top 0.5: LED1.A 18.5,55.01 18.5,54.98 R1.1
N$15  (via drill 0.5)
  Top 0.25: 82.25,13 82.26,13 R3.1 | IC3.P$36 101.5,36.41 101.5,36 101.75,35.75 v101.75,34.75
  Top 1: 82.25,13 v82.25,15.5
  Bottom 0.25: v101.75,34.75 101.75,31 86.25,15.5 v82.25,15.5
N$16  (via drill 0.5)
  Top 0.25: 89,13 88.91,13 R4.1 | IC3.P$35 102.5,36.91 v102.5,36.25
  Top 1: 89,13 v89,15.5
  Bottom 0.25: v102.5,36.25 102.75,36 102.75,33.75 102.5,33.5 102.5,30.75 89,17.25 v89,15.5
N$18
  Top 0.5: 84.75,7 84.99,7 R6.1 | 89.12,7 R7.2 | R3.2 85.1,12.75 84.99,12.75
  Top 1: 84.99,7 89.12,7 | R6.1 84.99,12.75
N$19
  Top 0.5: 91.75,7 91.92,7 R7.1 | 96.05,7 R8.2 | R4.2 91.67,12.75 91.92,12.75 92,12.75
  Top 1: 91.92,7 96.05,7 | R7.1 91.92,12.75
N$20
  Top 0.5: 103,7 102.91,7 R9.2 | R8.1 98.85,7 | R5.2 98.74,13 98.85,13
  Top 1: 98.85,7 102.91,7 | R8.1 98.85,13
N$21
  Top 0.25: IC2.14 61.75,14.77 61.75,14.65 C12.1
N$23
  Top 0.25: IC2.12 60.5,14.77 60.5,11.6 | 66.6,11.6 arc90 66.75,11.75 66.75,11.85 | 66.75,11.85 C12.2 | 66.75,11.85 66.75,12
  Top 0.5: 60.5,11.6 66.6,11.6
N$24
  Top 0.25: IC2.16 61.08,24.5 | 66.5,24.5 C10.1
  Top 0.5: 61.08,24.5 66.5,24.5
N$25
  Top 0.25: 66.5,19.75 C13.1 | IC2.17 60.42,19.75 61.25,19.75
  Top 0.5: 61.25,19.75 66.5,19.75
N$26
  Top 0.25: C15.1 63.5,13 61.08,13 IC2.13
N$28  (via drill 0.5)
  Top 0.25: R2.1 75.75,7 | IC3.P$37 100.75,35.91 v100.75,35.5
  Top 1: 75.75,7 v75.75,9.75
  Bottom 0.25: v75.75,9.75 75.75,17.25 86.25,17.25 | v100.75,35.5 99.25,35.5 99.25,29.75 86.75,17.25 86.25,17.25 | 86.25,17.25 86.5,17.25
N$30
  Top 0.5: D2.3 99,46.35 99,53.91 U$23.7
N$76  (via drill 0.5)
  Top 0.5: v88,49.25 88,49.15 | 127.5,51.5 127.5,51.43 U$4.2
  Top 1: 88,49.15 D5.1 | v127.5,48.75 127.5,51.43
  Bottom 1: v88,49.25 97,49.25 97,41.25 108.75,41.25 109.5,41.75 127.5,41.75 v127.5,48.75
N$78  (via drill 0.5)
  Top 0.5: v88.5,51.25 88.5,51.35 | IC4.11 78.75,59.28 v78.75,57 | R24.2 111,54.5 111,54 107.5,54 107.5,53.91 U$23.8 104.25,53.91 v104.25,54
  Top 1: 88.5,51.35 D5.3
  Bottom 0.5: 105.5,56.5 105.5,57 | 88.5,51.5 v88.5,51.25 104,51.25 | 104,54 v104.25,54
  Bottom 1: v88.5,51.25 105.5,51.25 105.5,56.5 105.5,61 78.75,61 v78.75,57 | 104,51.25 104,54
N$84
  Top 0.5: IC4.12 77.75,59.28 77.75,61.75 99,61.75 99,57.72 U$23.1
N$87
  Top 0.5: 91.5,54.15 91.5,54.25 | 91.5,54.15 IC8.2 | D5.2 91.5,49.15 91.5,54.15
PC-CTS
  Top 0.25: IC2.3 54.58,16.25 51.78,16.25
  Top 0.5: SV1.7 36.58,16.25 51.78,16.25
PC-DCD  (via drill 0.5)
  Top 0.25: IC2.1 53.27,13.25 49.25,13.25 49.25,12.5
  Top 0.5: 49.24,12.5 49.25,12.5 v49.25,11.5
  Bottom 0.5: SV1.1 36.58,8.5 49.25,8.5 v49.25,11.5
PC-DTR
  Top 0.25: IC2.27 53.92,19.75 54,19.75 | IC2.23 56.52,19.75 56.5,19.75 | IC2.18 59.77,19.75 59.25,19.75
  Top 0.406: 34,11 34,11.1 SV1.4
  Top 0.5: 59.25,19.75 56.5,19.75 54,19.75 38.5,19.75 38.5,21 32,21 32,11 34,11
PC-RTS
  Top 0.25: 34,16.25 34,17.5 55.23,17.5 IC2.4
  Top 0.5: 34,16.25 34.04,16.25 SV1.8
PC-RXD
  Top 0.25: IC2.2 53.92,10.25 50.5,10.25
  Top 0.5: 50.5,10.25 36.5,10.25 36.5,11.25 SV1.3
PC-TXD  (via drill 0.61)
  Top 0.25: v58.83,12.5 58.5,13.4 58.5,14.77 IC2.9
  Bottom 0.5: SV1.2 34.04,6.75 55,6.75 55,12.5 v58.83,12.5
PSEN  (via drill 0.5)
  Top 0.25: IC3.P$44 96.5,32.41 v96.75,32.5
  Top 0.5: 107.5,57.72 107.5,57.75 | 107.5,57.72 U$23.2 | 107.5,57.72 107.5,56.45 U$23.4 103,56.45 103,49 v100.5,49
  Top 1: v100.25,44 96.75,44 v96.75,39.25
  Bottom 1: v100.25,44 100.25,48.75 v100.5,49 | v96.75,32.5 v96.75,39.25
RESET  (via drill 0.5)
  Top 0.25: IC3.P$13 109.75,36.41 109.75,39 111.25,39 v111.25,40.25
  Top 0.5: IC4.8 82.69,59.5 84,59.5 | 84,59.5 PAD1.1 | v94.75,47.75 85.5,47.75 85.5,52 v84,52 | v84,58.5 84,59.5
  Bottom 0.5: v94.75,47.75 94.75,40.75 94.75,40.25 v111.25,40.25
  Bottom 1: v84,52 v84,58.5
RS
  Top 0.25: 129.48,36.5 129.5,36.5 | 129.48,36.5 SV2.3 | 129.48,36.5 125,36.5 125,21.5 104,21.5 IC3.P$54
RTS/CTS  (via drill 0.5, 0.61)
  Top 0.25: IC2.5 55.89,14.75 56.51,14.75 IC2.6 56.5,14.79 v56.5,18.5
  Top 0.5: 76.5,59.25 76.5,59.28 IC4.13 | 76.5,59.25 76.5,59 | v76.5,57 76.5,59.25
  Top 1: 76.5,31.5 76.5,31.25 88.75,31.25 arc90 89,31.5 arc-90 89,31.5 R19.2 | 76.5,31.5 v76.5,38 | v60.25,31.25 76.25,31.25 76.5,31.5
  Bottom 0.5: v56.5,18.5 56.5,20.75 60.25,20.75 v60.25,31.25
  Bottom 1: v76.5,38 v76.5,57
RW
  Top 0.25: SV2.6 132.02,33.75 132,33.75 132,35 125.75,35 125.75,20.75 103.5,20.75 IC3.P$53
RXD  (via drill 0.5)
  Top 0.25: v107.5,24.25 109.5,24.25 109.5,31.41 IC3.P$3 | IC2.8 57.83,8.5 58.75,8.5
  Top 0.5: 50.25,4 50.25,3.75 PAD5.1 58.13,3.75 58.13,8.5 58.75,8.5 v59.5,8.5
  Top 1: v89.25,24.25 v99.75,24.25
  Bottom 1: v99.75,24.25 v107.5,24.25 | v89.25,24.25 85,20 72.25,20 72.25,8.5 v59.5,8.5
SIG+  (via drill 0.5)
  Top 0.25: IC3.P$18 108.5,44 v107.75,44
  Top 0.5: ST2.3 105.04,71.75
  Top 1: 105.04,71.75 PAD3.1
  Bottom 0.25: 105.29,71.75 ST2.3
  Bottom 1: 105.29,71.75 105.5,71.75 106.5,72.75 109,72.75 109.75,72 109.75,44 v107.75,44
SIG-  (via drill 0.5)
  Top 0.25: IC3.P$19 108,42.75 v106.75,42.75
  Top 0.5: 105.29,74.25 ST2.4
  Top 1: v108.25,70.75 108.25,74.25 105.29,74.25 PAD4.1
  Bottom 1: v108.25,70.75 108.25,45.5 106.5,45.5 106.5,42.75 v106.75,42.75
TASTER_OUT  (via drill 0.5)
  Top 0.25: IC3.P$5 113.25,32.41 v113.25,34.25
  Bottom 0.25: SV2.16 132.02,21 132,21 130.75,22.5 128,22.5
  Bottom 1: 128,22.5 113.25,22.5 v113.25,34.25
TXD  (via drill 0.5)
  Top 0.25: 56.87,6.25 v56.75,6.25 57.17,6.25 IC2.7 | IC3.P$4 108,31.91 v108,30
  Top 0.5: v56.75,6.25 46.75,6.25 PAD6.1
  Top 1: v93,25.5 v99.75,25.5
  Bottom 0.25: 92.75,25.5 v93,25.5
  Bottom 1: v56.75,6.25 74,6.25 74,18.75 86,18.75 92.75,25.5 | v99.75,25.5 108,25.5 v108,30
VCC  (via drill 0.5, 0.61)
  Top 0.25: 106,27.75 IC3.P$58 106,30.41 | 106,30.41 106,30.25 104,30.25 104,30.41 IC3.P$48 97.41,30.41 96.5,29.5 95.15,29.5 95,29.5 | 106,30.41 106,35.41 IC3.P$11 113.5,35.41 113.5,37.5 | v62,17 59.77,17 IC2.11 59.77,10 | 114,37.5 114,37.41 IC3.P$15 IC3.P$14 | 95.15,33.5 95,33.5 95.09,33.41 IC3.P$42 | 69.5,10 C16.1 | 63.5,10 C15.2
  Top 0.5: 75.07,59.25 IC4.14 68.5,59.28 | 79.38,67.25 F1.4 | 127.6,56 U$4.1 | 122.75,56 R13.2 | R1.2 23,52.18 23,50.25 v27.5,50.25 | C8.2 115.1,40.6 115,40.5 C29.2 C32.2 | C32.2 115.1,37.6 115,37.5 | C32.2 115.1,37.5 114,37.5 113.5,37.5 | 59.77,10 63.5,10 69.5,10
  Top 1: IC1.3 55.5,53.84 C2.1 | IC8.3 84.5,56.35 84.5,55.5 68.5,55.5 | v70,55.5 68.5,55.5 | 122.75,56 122.75,43.5 129.48,43.5 SV2.1 | 122.75,56 127.6,56 | 122.75,56 122.75,59 115,59 111,63 C7.+ | 95.15,29.15 C33.2 | 95.15,29.15 95.15,29.5 95.15,33.5 C5.2 95.15,36.75 v95,36.75 | 95.15,29.15 95,29 | 68.5,67.25 65.25,67.25 | 68.5,67.25 79.38,67.25 | 65.25,67.25 arc-90 65,67.5 65,69.5 arc90 64.84,69.66 C4.1 | 65.25,67.25 65,67.25 | 68.5,55.5 68.5,59.28 C7.+ | C7.+ 68.5,67.25 | PAD9.1 68.5,69.31 68.5,67.25
  Bottom 1: IC1.3 55.5,53.84 55.5,53.5 | 70,36.75 94,36.75 | 94,36.75 94.5,36.75 | 70,36.75 v70,55.5 70,53.5 55.5,53.5 | v62,17 62,36.75 70,36.75 | 55.5,53.5 55.5,50.25 v27.5,50.25 | 94,36.75 v95,36.75
VCC_ANALOG  (via drill 0.5)
  Top 0.25: v84.5,48.75 84.5,45.25 102.5,45.25 IC3.P$30 102.5,39 103.5,39 IC3.P$28 103.5,40.5 | 82.25,67.5 82.25,67.36 F1.1
  Top 0.5: 90.5,65.33 90.5,65.25 | 105.25,66.75 105.25,66.58 ST2.1
  Top 1: 90.75,65.33 C6.+ 90.5,65.33 90.5,67.5 | v82.25,64.75 82.25,67.36 | 105.25,66.75 PAD2.1 95,66.75 95,67.5 90.5,67.5 | F1.1 82.5,67.36 82.5,67.5 90.5,67.5
  Bottom 0.5: v84.5,48.75 77.75,48.75 77.75,64.75 v82.25,64.75
VIN
  Top 0.25: 50.5,53.25 50.5,52.75
  Top 1: 50.5,52.75 C1.1 | 50.5,54.25 50.5,54 | 50.5,54.25 50.5,54.5 | 50.5,54 50.46,54 IC1.1 | 50.5,54 50.5,53.25 | 33,58.2 D1.C | 33,58.2 D3.C | D3.C 40,58.25 | C3.+ 33,66.89 33,58.2 | 33,58.2 44,58.2 | D3.C 44,58.2 | 44,58.2 44,54.25 50.5,54.25

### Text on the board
Top: Sig- | GND | Sig+ | CMP | VCC | GND_A | VCC_A | RESET | RESET | AC 8-15V | 1 | 4 | Kontrast | RS232 | Rev3.0 | Schur 4/2004 | TXD | RXD
Bottom: SLD
tDocu: Alle Maße Außenkontur: maximal -0,2mm fräsen | Alle Maße Durchbruch maximal +0.15mm fräsen | Achtung, LCD Display gespiegelt angeschlossen, für Pinheader auf der Rückseite des LCD
Bemassung: 53 | R7 | 12 | 4.5 | 9 | 17.25 | 16 | 78 | 12 | 12 | 23 | 20 | 98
